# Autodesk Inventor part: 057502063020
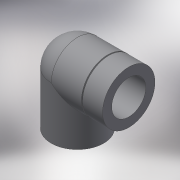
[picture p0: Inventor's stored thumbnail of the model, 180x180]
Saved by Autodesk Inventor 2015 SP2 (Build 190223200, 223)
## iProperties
Created: 2017-10
Part Number: 057502063020
Material: Generic
Description: ELBOW 90° THR-CEM REINF. R 63-2"
Document SubType Name: Modeling
Designer: KIM
Density: 1 g/cm^3
Appearance: Default
Author: KIM
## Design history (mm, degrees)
derived "057502.ipt"
feature "Solid1::057502.ipt"
tag "TaggingFeature1"
body "Solid1"
other parameters: "d0" = 74.5, "d1" = 73, "d3" = 71, "d4" = 73, "d6" = 90 deg, "d7" = 56.656, "d8" = 26, "d9" = 0, "d10" = 63, "d11" = 38, "d12" = 0, "d14" = 45.3248, "d16" = 28.328, "d17" = 0, "d18" = 0, "d19" = 73, "d20" = 29.8, "d21" = 0.5, "d22" = 0.5, "d_" = 63, "G_" = 56.656, "E_" = 73, "l_" = 38, "lt_" = 26, "Z_" = 33, "H_" = 111
